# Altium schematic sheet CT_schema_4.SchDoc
size 287 x 163 mm
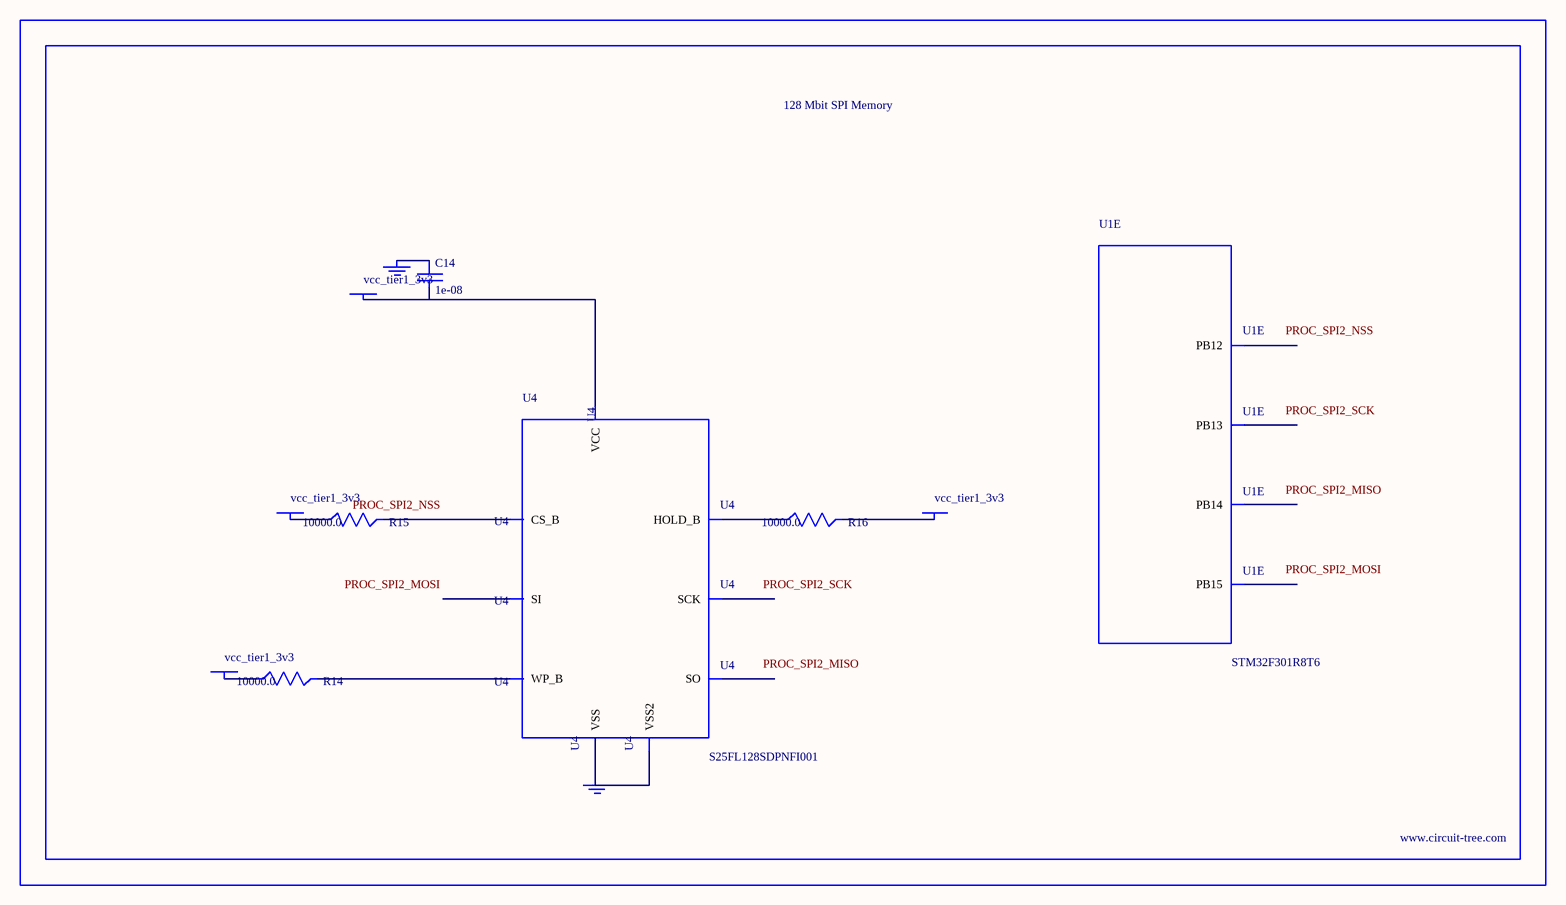
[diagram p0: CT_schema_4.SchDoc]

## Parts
BORDER3  (no value)
C14  1e-08  [C0402]
GND_INSTANCE_3_0  (no value)
GND_INSTANCE_3_1  (no value)
POWER_INSTANCE_3_0  vcc_tier1_3v3
POWER_INSTANCE_3_1  vcc_tier1_3v3
POWER_INSTANCE_3_2  vcc_tier1_3v3
POWER_INSTANCE_3_3  vcc_tier1_3v3
R14  10000.0  [R0603]
R15  10000.0  [R0603]
R16  10000.0  [R0603]
U1  STM32F301R8T6  [LQFP64]  (part E of 6)
U4  S25FL128SDPNFI001  [WNG008]

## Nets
NetC14_1: C14.1 GND_INSTANCE_3_0.0(GND)
NetC14_2: C14.2 POWER_INSTANCE_3_3.0(PWR) U4.8(VCC)
NetGND_INSTANCE_3_1_0: GND_INSTANCE_3_1.0(GND) U4.4(VSS) U4.PAD(VSS2)
NetPOWER_INSTANCE_3_0_0: POWER_INSTANCE_3_0.0(PWR) R15.1
NetPOWER_INSTANCE_3_1_0: POWER_INSTANCE_3_1.0(PWR) R14.1
NetPOWER_INSTANCE_3_2_0: POWER_INSTANCE_3_2.0(PWR) R16.2
NetR14_2: R14.2 U4.3(WP_B)
NetR15_2: R15.2 U4.1(CS_B)
NetR16_1: R16.1 U4.7(HOLD_B)

Not connected (* = marked no-connect by the designer): U1 33(PB12) 34(PB13) 35(PB14) 36(PB15); U4 2(SO) 5(SI) 6(SCK)

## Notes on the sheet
- Labels drawn without touching a wire or pin: PROC_SPI2_MISO, PROC_SPI2_MOSI, PROC_SPI2_NSS, PROC_SPI2_SCK

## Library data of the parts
BORDER3 = BORDER_PAGE3
C14 = C0402C103K3RAC
GND_INSTANCE_3_0 GND_INSTANCE_3_1 = GND
POWER_INSTANCE_3_0-POWER_INSTANCE_3_3 = PWR
R14-R16 = RC0603JR-0710KL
